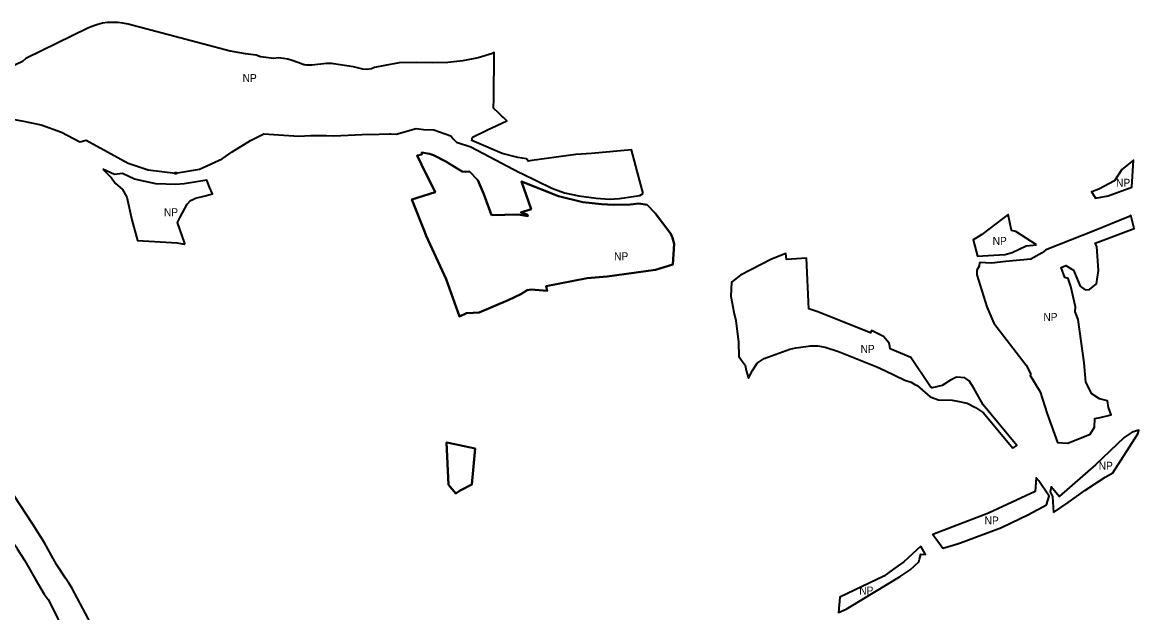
# Model space of a CAD drawing. Extents: x -650276 to -642489, y -1074311 to -1066658.
# Drawn here: x -645218 to -643544, y -1069701 to -1068817 of the extents above; entities that cross this region are included whole.
import ezdxf

# ---------------------------------------------------------------- set-up
doc = ezdxf.new("R2010")
doc.units = 0
doc.header["$LTSCALE"] = 4.8
doc.header["$PDMODE"] = 32
doc.header["$PDSIZE"] = 2.4
doc.layers.add('24', color=7, linetype='Continuous', lineweight=35)
doc.layers.add('48', color=7, linetype='Continuous', lineweight=35)
doc.layers.add('62', color=7, linetype='Continuous')

msp = doc.modelspace()

# ---------------------------------------------------------------- linework, layer by layer
at = {"layer": '24'}
for points in [[(-645322.13, -1069447.96), (-645309.62, -1069467.79), (-645303.57, -1069480.49), (-645268.57, -1069533.23), (-645242.75, -1069570.26), (-645230.42, -1069597.39), (-645227.27, -1069602.68), (-645225.7, -1069605.32), (-645214.76, -1069622.37), (-645198.41, -1069650.49), (-645185.17, -1069673.38), (-645179.12, -1069681.3), (-645170.3, -1069698.91), (-645158.43, -1069722.61), (-645153.44, -1069734.71), (-645140.27, -1069766.68), (-645123.84, -1069805.38), (-645108.74, -1069843.58), (-645094.42, -1069882.65), (-645083.31, -1069913.37), (-645071.53, -1069948.89), (-645063.96, -1069973.73), (-645063.23, -1069976.2), (-645062.57, -1069978.46)], [(-645017.46, -1069970.61), (-645018.28, -1069967.49), (-645024.45, -1069944.43), (-645032.85, -1069912.07), (-645043.5, -1069878.37), (-645051.78, -1069854.2), (-645063.26, -1069825.99), (-645095.1, -1069757.62), (-645118.98, -1069710.08), (-645143.56, -1069664.05), (-645148.8, -1069656.1), (-645150.3, -1069653.84), (-645153.33, -1069649.24), (-645166.67, -1069629), (-645184.88, -1069596.58), (-645202.56, -1069568.23), (-645230.1, -1069525.98)]]:
    msp.add_lwpolyline(points, dxfattribs=at)
at = {"layer": '48'}
msp.add_line((-644015.12, -1069254.24), (-644024.93, -1069250.23), dxfattribs=at)
for points in [[(-644783.84, -1068880.69), (-644787.7, -1068880.94), (-644791.66, -1068880.72), (-644794.33, -1068880.25), (-644795.57, -1068880.03), (-644799.27, -1068878.92), (-644813.52, -1068873.69), (-644819.79, -1068871.79), (-644826.24, -1068870.62), (-644834.48, -1068869.6), (-644840.86, -1068870.9), (-644861.04, -1068868.43), (-644867.05, -1068865.58), (-644883.44, -1068863.56), (-644900.37, -1068860.89), (-644906.18, -1068859.57), (-644947.96, -1068848.91), (-644998.7, -1068835.48), (-645059.46, -1068819.41), (-645067.04, -1068817.76), (-645074.66, -1068816.8), (-645082.34, -1068816.52), (-645090.01, -1068816.92), (-645097.47, -1068817.98), (-645104.87, -1068819.7), (-645112.38, -1068822.16), (-645119.5, -1068825.24), (-645212.72, -1068870.49), (-645217.45, -1068875.09), (-645235.76, -1068883.92)], [(-644286.94, -1069073.19), (-644293.51, -1069049.01), (-644304.6, -1069007.55), (-644364.53, -1069012.83), (-644387.91, -1069014.64), (-644453.95, -1069023.63), (-644459.67, -1069024.41), (-644461.74, -1069020.83), (-644475.09, -1069018.99), (-644498.28, -1069013.19), (-644544.02, -1068993.75), (-644543.05, -1068988.64), (-644523.4, -1068978.98), (-644519.61, -1068977.02), (-644514.16, -1068974.62), (-644491.31, -1068964.35), (-644496.63, -1068959.11), (-644498.8, -1068956.97), (-644503.61, -1068952.56), (-644511.47, -1068945.37), (-644510.75, -1068931.16), (-644510.37, -1068861.95), (-644512.71, -1068863.06), (-644534.67, -1068869.62), (-644557.21, -1068874.19), (-644580.06, -1068876.69), (-644602.97, -1068877.11), (-644626.34, -1068876.48), (-644653.09, -1068877.33), (-644674.5, -1068880.97), (-644689.63, -1068884.43), (-644694.39, -1068886.08), (-644700.83, -1068886.97), (-644707.32, -1068886.63), (-644721.29, -1068883.2), (-644751.36, -1068878.76), (-644753.71, -1068878.41), (-644761.63, -1068878.43), (-644770.17, -1068879.01), (-644783.84, -1068880.69)], [(-645413.29, -1069042.92), (-645396.53, -1069030.88), (-645371.56, -1069010.81), (-645350.17, -1068993.33), (-645328.55, -1068980.37), (-645311.99, -1068972.74), (-645292.77, -1068966.91), (-645275.45, -1068964.38), (-645255.21, -1068962.49), (-645232.4, -1068961.67), (-645218.85, -1068964.3), (-645189.84, -1068969.91), (-645159.37, -1068981.11), (-645131.73, -1068995.69), (-645122.25, -1068993.21), (-645090.35, -1069010.56), (-645059.3, -1069027.45), (-645029.47, -1069037.71), (-644988.11, -1069042.51)], [(-644875.57, -1068993.47), (-644855.56, -1068983.38), (-644803.31, -1068986.97), (-644785.78, -1068986.13), (-644761.88, -1068986.27), (-644750.67, -1068986.34), (-644708.6, -1068984.54), (-644683, -1068984.03), (-644667.57, -1068983.47), (-644665.41, -1068983.39), (-644657.61, -1068983.91)], [(-644657.61, -1068983.91), (-644627.41, -1068975.6), (-644616.36, -1068976.86), (-644600.67, -1068977.77), (-644575.29, -1068986.48), (-644572.05, -1068991.08), (-644567.09, -1068996.26), (-644545.54, -1069003.12), (-644472.37, -1069041.44), (-644468.95, -1069043.11), (-644424.01, -1069065.01), (-644404.96, -1069071.76), (-644383.55, -1069076.57), (-644357.4, -1069079.84), (-644337.6, -1069081.29), (-644322.55, -1069080.62), (-644319.2, -1069079.82), (-644292.27, -1069076.05), (-644286.94, -1069073.19)], [(-644988.11, -1069042.51), (-644952.47, -1069036.35), (-644918.04, -1069020.91), (-644903.21, -1069010.69), (-644875.57, -1068993.47)], [(-644619.1, -1069011.81), (-644618.8, -1069014.7), (-644625.69, -1069015.84)], [(-644625.69, -1069015.84), (-644619.54, -1069029.55), (-644598.81, -1069071.02)], [(-644583.05, -1069025.29), (-644601.43, -1069015.74), (-644607.16, -1069013.56), (-644619.1, -1069011.81)], [(-645096.97, -1069036.63), (-645084.19, -1069049.55), (-645078.47, -1069057.37), (-645067.57, -1069067.16)], [(-644993.99, -1069146.57), (-644994.006, -1069146.673), (-644986.221, -1069147.139), (-644974.505, -1069149.05), (-644974.34, -1069147.85), (-644985.15, -1069116.67), (-644981.3, -1069108.22), (-644970.84, -1069088.8), (-644965.95, -1069083.67), (-644962.15, -1069081.85), (-644958.25, -1069079.99), (-644943.69, -1069076.34), (-644932.95, -1069073.65), (-644937.058, -1069063.404), (-644937.057, -1069063.403), (-644937.05, -1069063.4), (-644941.27, -1069052.9), (-644975.19, -1069058.65), (-644987.99, -1069059.67), (-645017.77, -1069058.35), (-645049.91, -1069051.48), (-645067.65, -1069043.18), (-645079.65, -1069044.32), (-645096.97, -1069036.63)], [(-645096.97, -1069036.63), (-645084.19, -1069049.55), (-645080.589, -1069054.473)], [(-644553.62, -1069040.53), (-644558.56, -1069039.86), (-644563.19, -1069037.21), (-644583.05, -1069025.29)], [(-645080.589, -1069054.473), (-645078.47, -1069057.37), (-645067.57, -1069067.16), (-645061.2, -1069078.47), (-645053.61, -1069112.32), (-645044.97, -1069143.38), (-644993.99, -1069146.57)], [(-644535.13, -1069053.18), (-644547.31, -1069040.11), (-644553.62, -1069040.53)], [(-644514.47, -1069105.62), (-644525.83, -1069073.84), (-644535.13, -1069053.18)], [(-644598.81, -1069071.02), (-644633.66, -1069082), (-644614.41, -1069131.08), (-644612.3, -1069136.45), (-644582.29, -1069201.27), (-644562.47, -1069257.56), (-644552.01, -1069252.24), (-644541.83, -1069251.66), (-644532.71, -1069251.12), (-644489.27, -1069233.04), (-644470.64, -1069224), (-644460.97, -1069217.61)], [(-644281.26, -1069090.19), (-644293.62, -1069088.17), (-644306.29, -1069089.37), (-644331.44, -1069090), (-644349.32, -1069089.22), (-644377.36, -1069085.89), (-644414.04, -1069076.75), (-644469.28, -1069054.8), (-644454.75, -1069096.51)], [(-644454.75, -1069096.51), (-644470.37, -1069101.55), (-644461.01, -1069104.36), (-644459.82, -1069106.73), (-644474.33, -1069104.22), (-644514.47, -1069105.62)], [(-644242.48, -1069179.49), (-644240.67, -1069148.58), (-644243.14, -1069139.47), (-644245.65, -1069133.66), (-644269.11, -1069102.31), (-644281.26, -1069090.19)], [(-643697.29, -1069149.7), (-643728.49, -1069129.95), (-643734.75, -1069128.3), (-643739.66, -1069104.58), (-643747.75, -1069110.71), (-643779.31, -1069134.63), (-643784.55, -1069137.77), (-643792.04, -1069142.27), (-643785.6, -1069166.98), (-643769.71, -1069166.04)], [(-643555.98, -1069105.57), (-643559.5, -1069107.98), (-643610.81, -1069129.04), (-643681.63, -1069157.04), (-643683.68, -1069157.86), (-643688.91, -1069162.16), (-643705.7, -1069171.37), (-643743.11, -1069175.08), (-643764.86, -1069177.58), (-643782.92, -1069176.24)], [(-643607.02, -1069152.34), (-643609.08, -1069147.64), (-643550.79, -1069125.24), (-643555.98, -1069105.57)], [(-643769.71, -1069166.04), (-643743.99, -1069164.43), (-643733.83, -1069161.46), (-643712.74, -1069151.46), (-643697.29, -1069149.7)], [(-643707.23, -1069344.52), (-643691.6, -1069370.3), (-643681.09, -1069403.24), (-643665.87, -1069446.1), (-643650.28, -1069446.91), (-643616.78, -1069433.81), (-643610.18, -1069422.91), (-643609.6, -1069409.99), (-643601.9, -1069408.43), (-643585.19, -1069404.76), (-643589.52, -1069393.88), (-643590.89, -1069383.9), (-643602.92, -1069380.53), (-643614.35, -1069373.28), (-643623.28, -1069355.47), (-643625.9, -1069326.77), (-643634.56, -1069262.02), (-643639.23, -1069250.38), (-643638.72, -1069242.94), (-643645.61, -1069212.25), (-643649.84, -1069200.4), (-643654.57, -1069198.77), (-643660.22, -1069184.11), (-643653.05, -1069180.98), (-643641.84, -1069187.68), (-643631.66, -1069211.67), (-643624.38, -1069217.27), (-643617.64, -1069217), (-643607.37, -1069208.43), (-643604.38, -1069188.48), (-643607.02, -1069152.34)], [(-644094.79, -1069171.27), (-644141.24, -1069195.17), (-644154.36, -1069206.06), (-644155.37, -1069226.72), (-644151.11, -1069250.7), (-644148.22, -1069263.22), (-644144.05, -1069295.67)], [(-644024.93, -1069250.23), (-644038.83, -1069245.65), (-644042.37, -1069169.77), (-644071.97, -1069171.72), (-644073.35, -1069162.84), (-644094.79, -1069171.27)], [(-644460.97, -1069217.61), (-644454.87, -1069217.05), (-644430.91, -1069218.82), (-644432.53, -1069212.02), (-644371.08, -1069199.84), (-644340.83, -1069197.13), (-644268.7, -1069187.42), (-644242.48, -1069179.49)], [(-643782.92, -1069176.24), (-643783.2, -1069181.85), (-643786.97, -1069188.11), (-643786.89, -1069195.02), (-643771.86, -1069242.77), (-643761.21, -1069267.12), (-643712.78, -1069330.24)], [(-643732.705, -1069454.79), (-643726.74, -1069450.72), (-643777.27, -1069389.71), (-643791.02, -1069364.54), (-643798.1, -1069353.51), (-643804.83, -1069348.99), (-643817.06, -1069348.14), (-643826.21, -1069352.92), (-643838.69, -1069360.79), (-643853.56, -1069364.44), (-643856.43, -1069362.68), (-643885.63, -1069318.72), (-643916.78, -1069305.89), (-643917.36, -1069302.04), (-643918.08, -1069297.33), (-643926.74, -1069287.37), (-643944.89, -1069278.32), (-643946.16, -1069281.84), (-644015.12, -1069254.24)], [(-644144.05, -1069295.67), (-644143.54, -1069317.05), (-644138.55, -1069324.23), (-644134.15, -1069330.45), (-644132.52, -1069338.02), (-644129.09, -1069349.83), (-644123.21, -1069338.41), (-644116.33, -1069327.36), (-644105.5, -1069320.03), (-644067.08, -1069306.15), (-644058.05, -1069304.02), (-644054.35, -1069303.55)], [(-644054.35, -1069303.55), (-644035.89, -1069301.02), (-644025.24, -1069301.38), (-644014.19, -1069303.36), (-643993.91, -1069309.57), (-643936.87, -1069332.93), (-643924.42, -1069338.29), (-643894.84, -1069352.76), (-643885.22, -1069355.58), (-643879.48, -1069359.13), (-643876.34, -1069360.61), (-643856.58, -1069377.59), (-643844.28, -1069382.26), (-643823.72, -1069382.61), (-643815.93, -1069384.23), (-643801.36, -1069387.23), (-643788.63, -1069393.7), (-643776.78, -1069401.87), (-643732.705, -1069454.79)], [(-643712.78, -1069330.24), (-643705.74, -1069343.54), (-643707.23, -1069344.52)]]:
    msp.add_lwpolyline(points, dxfattribs=at)
for points in [[(-644514.47, -1069105.62), (-644474.33, -1069104.22), (-644459.82, -1069106.73), (-644461.01, -1069104.36), (-644470.37, -1069101.55), (-644454.75, -1069096.51), (-644469.28, -1069054.8), (-644414.04, -1069076.75), (-644377.36, -1069085.89), (-644349.32, -1069089.22), (-644331.44, -1069090), (-644306.29, -1069089.37), (-644293.62, -1069088.17), (-644281.26, -1069090.19), (-644269.11, -1069102.31), (-644245.65, -1069133.66), (-644243.14, -1069139.47), (-644240.67, -1069148.58), (-644242.48, -1069179.49), (-644268.7, -1069187.42), (-644340.83, -1069197.13), (-644371.08, -1069199.84), (-644432.53, -1069212.02), (-644430.91, -1069218.82), (-644454.87, -1069217.05), (-644460.97, -1069217.61), (-644470.64, -1069224), (-644489.27, -1069233.04), (-644532.71, -1069251.12), (-644541.83, -1069251.66), (-644552.01, -1069252.24), (-644562.47, -1069257.56), (-644582.29, -1069201.27), (-644612.3, -1069136.45), (-644614.41, -1069131.08), (-644633.66, -1069082), (-644598.81, -1069071.02), (-644619.54, -1069029.55), (-644625.69, -1069015.84), (-644618.8, -1069014.7), (-644619.1, -1069011.81), (-644607.16, -1069013.56), (-644601.43, -1069015.74), (-644583.05, -1069025.29), (-644563.19, -1069037.21), (-644558.56, -1069039.86), (-644553.62, -1069040.53), (-644547.31, -1069040.11), (-644535.13, -1069053.18), (-644525.83, -1069073.84)], [(-643589.94, -1069076.36), (-643554.17, -1069063.59), (-643551.72, -1069023.19), (-643569.44, -1069037.24), (-643580.21, -1069053.96), (-643603.72, -1069066.5), (-643614.36, -1069070.29), (-643614.82, -1069070.45), (-643610.31, -1069077.52), (-643608.65, -1069080.11)], [(-643671.53, -1069551.1), (-643649.94, -1069535.93), (-643624.65, -1069517.85), (-643605.97, -1069505.47), (-643594.49, -1069498.17), (-643582.77, -1069491.76), (-643545.07, -1069432.89), (-643544.06, -1069427.6), (-643553.7, -1069430.44), (-643565.92, -1069438.4), (-643608.89, -1069479.72), (-643663.46, -1069526.87), (-643675.32, -1069512.62), (-643676.9, -1069519.91), (-643673.34, -1069527.08)], [(-644578.92, -1069446.8), (-644539, -1069454.88), (-644543.99, -1069508.88), (-644561.24, -1069518.27), (-644567.976, -1069522.752), (-644579.047, -1069509.608), (-644581.87, -1069446.28)], [(-644578.92, -1069446.8), (-644581.87, -1069446.28), (-644579.047, -1069509.608), (-644567.976, -1069522.752), (-644561.24, -1069518.27), (-644543.99, -1069508.88), (-644539, -1069454.88)], [(-643845.304, -1069594.087), (-643837.72, -1069604.62), (-643822.06, -1069600.07), (-643811.16, -1069596.45), (-643749.64, -1069573.35), (-643709.33, -1069554.14), (-643682.27, -1069539.41), (-643678.24, -1069526.44), (-643693.95, -1069503.38), (-643697.85, -1069499.21), (-643699.23, -1069519.48), (-643769.08, -1069551.96), (-643852.51, -1069584.08)], [(-643870.697, -1069601.241), (-643895.951, -1069625.069), (-643909.616, -1069634.267), (-643926.229, -1069646.367), (-643992.34, -1069677.76), (-643994.36, -1069701.05), (-643982.84, -1069695.93), (-643977.582, -1069692.76), (-643901.55, -1069646.92), (-643886.62, -1069636.87), (-643873.82, -1069625.05), (-643872.55, -1069620.75), (-643870.44, -1069613.56), (-643863.92, -1069613.9)]]:
    msp.add_lwpolyline(points, close=True, dxfattribs=at)
msp.add_point((-644988.11, -1069042.51), dxfattribs=at)

# ---------------------------------------------------------------- texts
at = {"layer": '62', "width": 0.95}
for p in [(-644887.583, -1068906.041), (-643577.985, -1069062.967), (-645005.583, -1069107.041), (-643762.985, -1069149.967), (-644330.583, -1069173.041), (-643686.985, -1069263.967), (-643961.069, -1069311.925), (-643603.985, -1069486.967), (-643774.985, -1069568.967), (-643962.985, -1069673.967)]:
    msp.add_text('NP', height=12, dxfattribs=at).set_placement(p)

doc.saveas('drawing.dxf')
